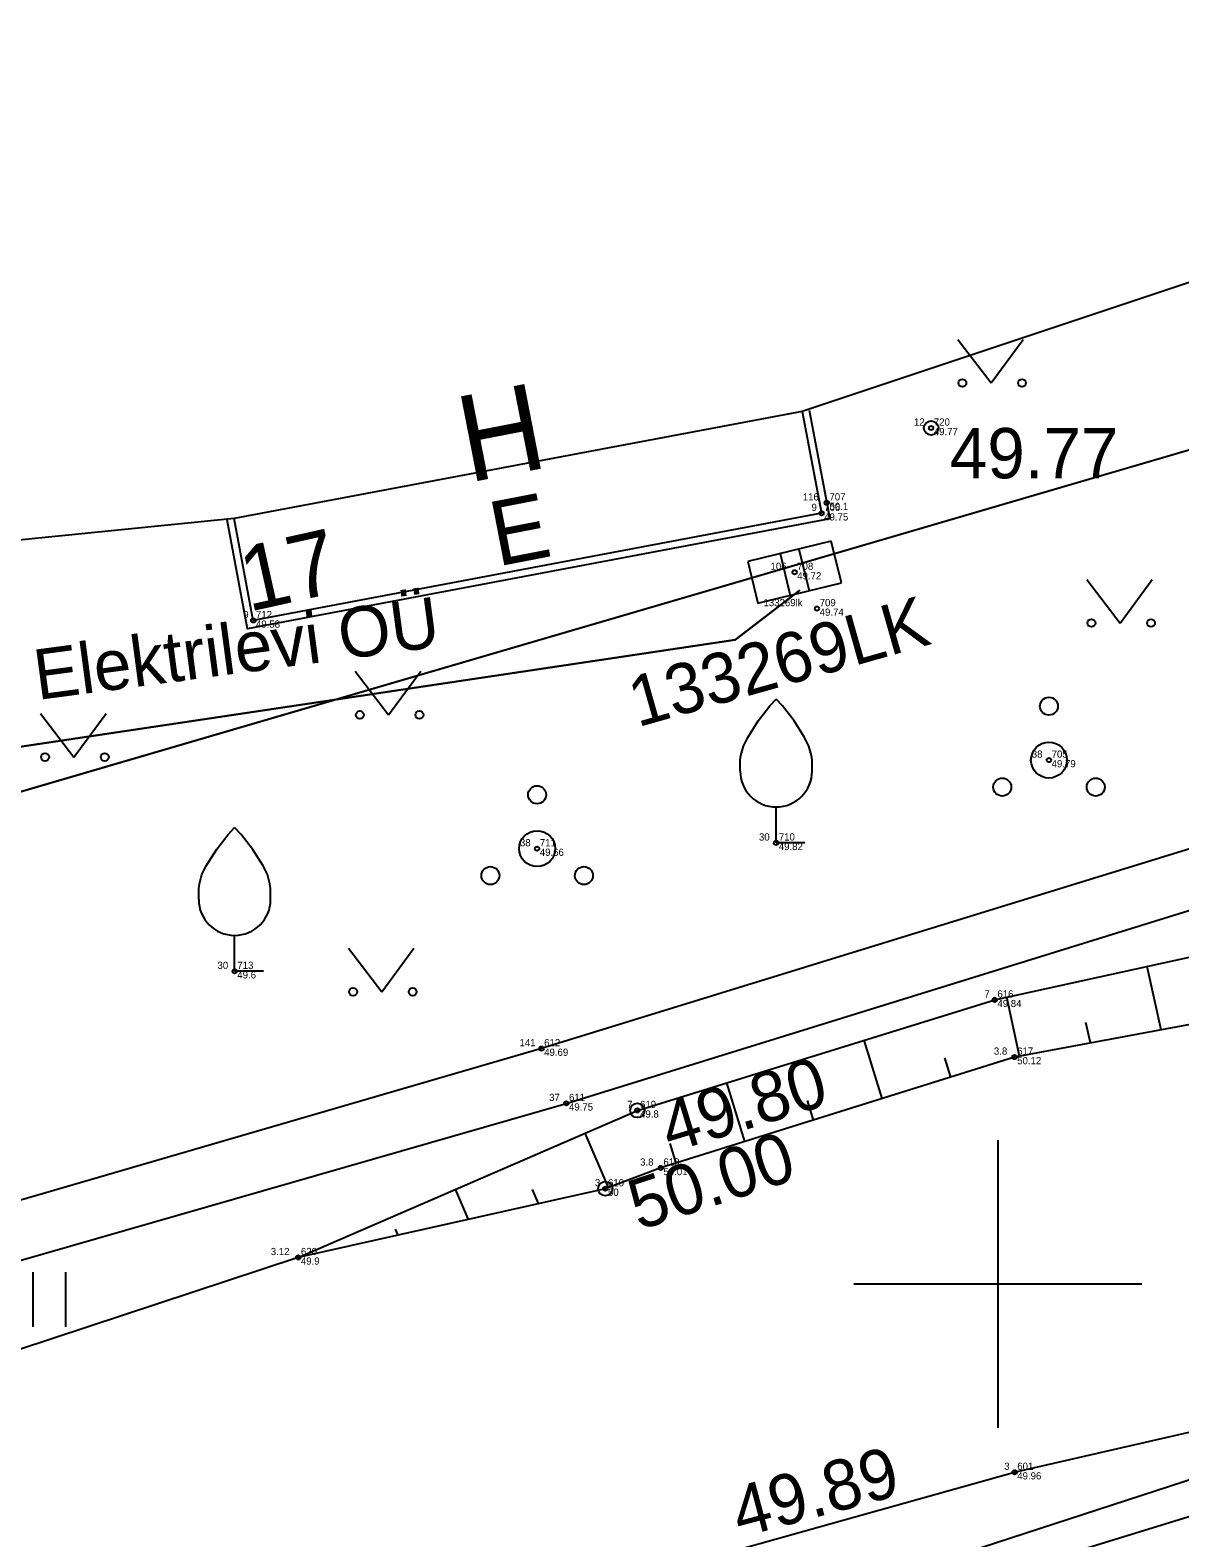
# Model space of a CAD drawing. Extents: x 543497 to 552146, y 6567125 to 6579845.
# Drawn here: x 546036.55 to 546052.53, y 6577696.47 to 6577717.44 of the extents above; entities that cross this region are included whole.
import ezdxf

# ---------------------------------------------------------------- set-up
doc = ezdxf.new("R2010")
doc.units = 0
for name, color, linetype in [('xref_Kangru tee 1_geodeesia$0$AED', 7, 'Continuous'), ('xref_Kangru tee 1_geodeesia$0$ELRAJATISMP', 7, 'Continuous'), ('xref_Kangru tee 1_geodeesia$0$HALJASTUS', 7, 'Continuous'), ('xref_Kangru tee 1_geodeesia$0$HOONE', 7, 'Continuous'), ('xref_Kangru tee 1_geodeesia$0$HOONEDET', 7, 'Continuous'), ('xref_Kangru tee 1_geodeesia$0$korgus-EH2000', 7, 'Continuous'), ('xref_Kangru tee 1_geodeesia$0$mootkood', 7, 'Continuous'), ('xref_Kangru tee 1_geodeesia$0$MOOTKORG-eh2000', 7, 'Continuous'), ('xref_Kangru tee 1_geodeesia$0$mootmpunkt', 7, 'Continuous'), ('xref_Kangru tee 1_geodeesia$0$MOOTNR', 7, 'Continuous'), ('xref_Kangru tee 1_geodeesia$0$MOOTPIIR', 7, 'Continuous'), ('xref_Kangru tee 1_geodeesia$0$MPKAABEL', 7, 'Continuous'), ('xref_Kangru tee 1_geodeesia$0$PIIR', 7, 'Continuous'), ('xref_Kangru tee 1_geodeesia$0$PUU', 7, 'Continuous'), ('xref_Kangru tee 1_geodeesia$0$RELJEEF', 7, 'Continuous'), ('xref_Kangru tee 1_geodeesia$0$SITRASS', 7, 'Continuous'), ('xref_Kangru tee 1_geodeesia$0$TEE', 7, 'Continuous'), ('xref_Kangru tee 1_geodeesia$0$vork', 7, 'Continuous')]:
    doc.layers.add(name, color=color, linetype=linetype)

# ---------------------------------------------------------------- blocks, each defined once
blk = doc.blocks.new('xref_Kangru tee 1_geodeesia$0$PQQSAS')
for centre, radius in [((0, 1.5), 0.25), ((0, 0), 0.5), ((-1.3, -0.75), 0.25), ((1.3, -0.75), 0.25)]:
    blk.add_circle(centre, radius)
blk = doc.blocks.new('xref_Kangru tee 1_geodeesia$0$VILJA1')
for p, q in [((0, 0), (0, 1)), ((0.8, 0), (0, 0))]:
    blk.add_line(p, q)
for points in [[(-1, 2), (-1, 2.3), (-0.98, 2.43), (-0.91, 2.69), (-0.79, 2.93), (-0.5, 3.4), (-0.18, 3.81), (0, 4)], [(1, 2), (1, 2.3), (0.98, 2.43), (0.91, 2.69), (0.79, 2.93), (0.5, 3.4), (0.18, 3.81), (0, 4)]]:
    blk.add_lwpolyline(points)
blk.add_arc((0, 2), 1, 180, 0)
blk = doc.blocks.new('xref_Kangru tee 1_geodeesia$0$hein')
for p, q in [((-0.455, 0.761), (-0.455, -0.761)), ((0.455, 0.761), (0.455, -0.761))]:
    blk.add_line(p, q)
blk = doc.blocks.new('xref_Kangru tee 1_geodeesia$0$MURU')
for p, q in [((-0.927, 1.213), (0, 0)), ((0, 0), (0.891, 1.213))]:
    blk.add_line(p, q)
for centre in [(-0.802, 0), (0.856, 0)]:
    blk.add_circle(centre, 0.11)
blk = doc.blocks.new('xref_Kangru tee 1_geodeesia$0$ELKAPP')
for p, q in [((1.195, 0.597), (-1.195, 0.597)), ((-1.195, 0.597), (-1.195, -0.597)), ((-0.271, 0.597), (-0.271, -0.597)), ((0.271, 0.597), (0.271, -0.597)), ((1.195, -0.597), (1.195, 0.597)), ((-1.195, -0.597), (1.195, -0.597))]:
    blk.add_line(p, q)
blk = doc.blocks.new('xref_Kangru tee 1_geodeesia$0$VKORIS')
for p, q in [((0, 4), (0, -4)), ((-4, 0), (4, 0))]:
    blk.add_line(p, q)

msp = doc.modelspace()

# ---------------------------------------------------------------- linework, layer by layer
at = {"layer": 'xref_Kangru tee 1_geodeesia$0$AED'}
msp.add_lwpolyline([(546059.838, 6577715.079), (546060.599, 6577708.494), (546043.656, 6577703.273), (546024.552, 6577697.712), (546024.121, 6577700.643), (546019.535, 6577705.044)], dxfattribs=at)
at = {"layer": 'xref_Kangru tee 1_geodeesia$0$HALJASTUS'}
msp.add_lwpolyline([(546028.276, 6577697.987), (546044.001, 6577702.512), (546059.639, 6577707.358), (546060.383, 6577708.688), (546059.561, 6577713.105)], dxfattribs=at)
at = {"layer": 'xref_Kangru tee 1_geodeesia$0$HOONE'}
msp.add_lwpolyline([(546047.281, 6577712.138), (546047.549, 6577710.72), (546039.649, 6577709.229), (546039.381, 6577710.647)], dxfattribs=at)
at = {"layer": 'xref_Kangru tee 1_geodeesia$0$HOONEDET'}
msp.add_lwpolyline([(546047.378, 6577712.157), (546047.664, 6577710.641), (546039.57, 6577709.114), (546039.284, 6577710.629)], dxfattribs=at)
at = {"layer": 'xref_Kangru tee 1_geodeesia$0$korgus-EH2000'}
for centre in [(546049.073, 6577711.907), (546044.989, 6577702.414), (546044.543, 6577701.325)]:
    msp.add_circle(centre, 0.1, dxfattribs=at)
at = {"layer": 'xref_Kangru tee 1_geodeesia$0$mootmpunkt'}
for centre in [(546049.073, 6577711.907), (546047.622, 6577710.866), (546047.549, 6577710.72), (546047.174, 6577709.901), (546047.486, 6577709.395), (546039.649, 6577709.229), (546050.711, 6577707.287), (546046.918, 6577706.135), (546043.595, 6577706.055), (546039.39, 6577704.349), (546049.957, 6577703.951), (546043.656, 6577703.273), (546050.232, 6577703.156), (546044.001, 6577702.512), (546044.989, 6577702.414), (546045.314, 6577701.613), (546044.543, 6577701.325), (546040.274, 6577700.368), (546050.233, 6577697.38)]:
    msp.add_circle(centre, 0.03, dxfattribs=at)
at = {"layer": 'xref_Kangru tee 1_geodeesia$0$MOOTPIIR'}
msp.add_lwpolyline([(546091.362, 6577730.835), (546076.174, 6577727.357), (546069.665, 6577722.185), (546069.859, 6577718.295), (546059.732, 6577716.292), (546047.281, 6577712.138), (546039.381, 6577710.647), (546032.006, 6577709.907), (546022.782, 6577705.611), (546019.535, 6577705.044), (546019.82, 6577703.764), (546018.234, 6577702.863), (546014.32, 6577701.586), (545991.87, 6577693.345), (545969.52, 6577687.243)], dxfattribs=at)
at = {"layer": 'xref_Kangru tee 1_geodeesia$0$MPKAABEL'}
for points in [[(546047.243, 6577709.648), (546047.243, 6577709.648), (546047.243, 6577709.648), (546047.243, 6577709.648), (546047.243, 6577709.648), (546046.35, 6577708.96), (546028.9, 6577706.35), (546020.34, 6577704.86), (546016.42, 6577703.78), (546014.701, 6577704.002)], [(546014.701, 6577704.002), (546016.42, 6577703.78), (546020.34, 6577704.86), (546028.9, 6577706.35), (546028.9, 6577706.35), (546046.35, 6577708.96), (546047.243, 6577709.648), (546047.243, 6577709.648), (546047.243, 6577709.648), (546047.243, 6577709.648)]]:
    msp.add_lwpolyline(points, dxfattribs=at)
at = {"layer": 'xref_Kangru tee 1_geodeesia$0$PIIR'}
for points in [[(545983.53, 6577775.51), (546081.11, 6577806.12), (546096.86, 6577764.18), (546079.41, 6577756.98), (546054.12, 6577754.83), (546055.48, 6577740.79), (546080.65, 6577742.83), (546099.69, 6577747.34), (546110.26, 6577728.46), (545969.55, 6577687.28), (545983.53, 6577775.51)], [(545526.72, 6577483.94), (545567.61, 6577503.92), (545600.27, 6577519.26), (545639.76, 6577537.43), (545673.8, 6577552.72), (545712.72, 6577569.73), (545743.83, 6577582.87), (545764.02, 6577591.24), (545805.47, 6577607.21), (545907.89, 6577644.25), (545925.88, 6577650.4), (545918.84, 6577672.45), (545921.7, 6577673.29), (545969.55, 6577687.28), (546110.26, 6577728.46), (546113.86, 6577718.6), (546117.94, 6577707.48), (546328.8, 6577761.79)]]:
    msp.add_lwpolyline(points, dxfattribs=at)
at = {"layer": 'xref_Kangru tee 1_geodeesia$0$PUU'}
msp.add_lwpolyline([(546117.866, 6577717.426), (546113.699, 6577716.286), (546090.767, 6577709.285), (546067.25, 6577701.449), (546060.951, 6577699.314), (546047.057, 6577695.034), (546019.897, 6577686.031), (545997.772, 6577678.867)], dxfattribs=at)
at = {"layer": 'xref_Kangru tee 1_geodeesia$0$RELJEEF'}
for p, q in [((546052.269, 6577703.535), (546052.076, 6577704.416)), ((546050.303, 6577703.169), (546050.123, 6577703.987)), ((546051.286, 6577703.352), (546051.224, 6577703.635)), ((546048.392, 6577702.579), (546048.142, 6577703.389)), ((546049.347, 6577702.878), (546049.263, 6577703.147)), ((546046.484, 6577701.98), (546046.231, 6577702.798)), ((546047.438, 6577702.279), (546047.354, 6577702.551)), ((546044.589, 6577701.342), (546044.261, 6577702.098)), ((546045.53, 6577701.681), (546045.445, 6577701.955)), ((546042.64, 6577700.898), (546042.458, 6577701.316)), ((546043.615, 6577701.117), (546043.53, 6577701.314)), ((546041.664, 6577700.68), (546041.628, 6577700.761))]:
    msp.add_line(p, q, dxfattribs=at)
msp.add_lwpolyline([(546040.274, 6577700.368), (546044.989, 6577702.414), (546049.957, 6577703.951), (546056.042, 6577705.287), (546059.025, 6577705.273)], dxfattribs=at)
at = {"layer": 'xref_Kangru tee 1_geodeesia$0$SITRASS'}
msp.add_lwpolyline([(545908.485, 6577643.705), (545911.194, 6577646.612), (545925.706, 6577656.002), (545927.481, 6577656.734), (545938.042, 6577659.913), (545948.418, 6577663.054), (545958.853, 6577666.457), (545971.932, 6577670.246), (545983.129, 6577674.156), (545994.132, 6577677.914), (546005.032, 6577681.831), (546015.499, 6577685.452), (546025.557, 6577688.556), (546030.559, 6577690.213), (546046.952, 6577695.414), (546066.518, 6577701.793), (546078.972, 6577705.852), (546100.203, 6577712.621), (546110.553, 6577715.537), (546117.41, 6577717.31), (546125.411, 6577719.428), (546136.464, 6577722.314), (546141.561, 6577723.784)], dxfattribs=at)
at = {"layer": 'xref_Kangru tee 1_geodeesia$0$TEE'}
for points in [[(545971.433, 6577672.366), (545997.276, 6577680.49), (546019.075, 6577687.637), (546046.227, 6577696.261), (546050.233, 6577697.38), (546060.833, 6577699.813), (546062.092, 6577700.466), (546063.421, 6577702.15), (546066.8, 6577702.917), (546090.631, 6577711.146), (546112.837, 6577718.304), (546121.35, 6577721.07), (546120.4, 6577725.737), (546111.41, 6577723.208), (546088.914, 6577715.843), (546065.816, 6577706.486), (546065.244, 6577706.703), (546065.037, 6577707.357), (546065.171, 6577709.425), (546065.38, 6577710.653), (546064.96, 6577714.947), (546067.921, 6577716.792), (546070.994, 6577716.678), (546072.733, 6577718.476)], [(546059.977, 6577715.174), (546061.866, 6577715.362), (546062.121, 6577710.624), (546061.045, 6577709.272), (546060.882, 6577708.001), (546060.893, 6577706.804), (546060.369, 6577705.849), (546059.158, 6577705.188), (546056.387, 6577704.301), (546050.232, 6577703.156), (546045.314, 6577701.613), (546044.543, 6577701.325), (546040.274, 6577700.368), (546017.855, 6577692.963), (545995.651, 6577685.598), (545969.99, 6577676.752), (545949.859, 6577670.253), (545932.117, 6577664.712), (545929.387, 6577664.046), (545924.424, 6577663.904), (545920.826, 6577664.534), (545918.964, 6577665.384), (545916.564, 6577667.08), (545914.824, 6577669.08)]]:
    msp.add_lwpolyline(points, dxfattribs=at)

# ---------------------------------------------------------------- block references
at = {"layer": 'xref_Kangru tee 1_geodeesia$0$ELRAJATISMP', "xscale": 0.5, "yscale": 0.5, "rotation": 13.580242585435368}
msp.add_blockref('xref_Kangru tee 1_geodeesia$0$ELKAPP', (546047.174, 6577709.901), dxfattribs=at)
at = {"layer": 'xref_Kangru tee 1_geodeesia$0$HALJASTUS', "xscale": 0.5, "yscale": 0.5}
for name, p in [('xref_Kangru tee 1_geodeesia$0$MURU', (546049.908, 6577712.533)), ('xref_Kangru tee 1_geodeesia$0$MURU', (546051.702, 6577709.194)), ('xref_Kangru tee 1_geodeesia$0$MURU', (546041.531, 6577707.916)), ('xref_Kangru tee 1_geodeesia$0$MURU', (546037.156, 6577707.329)), ('xref_Kangru tee 1_geodeesia$0$MURU', (546041.437, 6577704.063)), ('xref_Kangru tee 1_geodeesia$0$hein', (546036.812, 6577699.785))]:
    msp.add_blockref(name, p, dxfattribs=at)
at = {"layer": 'xref_Kangru tee 1_geodeesia$0$PUU', "xscale": 0.5, "yscale": 0.5}
for name, p in [('xref_Kangru tee 1_geodeesia$0$VILJA1', (546046.918, 6577706.135)), ('xref_Kangru tee 1_geodeesia$0$PQQSAS', (546050.711, 6577707.287)), ('xref_Kangru tee 1_geodeesia$0$PQQSAS', (546043.595, 6577706.055)), ('xref_Kangru tee 1_geodeesia$0$VILJA1', (546039.39, 6577704.349))]:
    msp.add_blockref(name, p, dxfattribs=at)
at = {"layer": 'xref_Kangru tee 1_geodeesia$0$vork', "xscale": 0.5, "yscale": 0.5}
msp.add_blockref('xref_Kangru tee 1_geodeesia$0$VKORIS', (546050, 6577700), dxfattribs=at)

# ---------------------------------------------------------------- texts
at = {"layer": 'xref_Kangru tee 1_geodeesia$0$ELRAJATISMP'}
msp.add_text('133269LK', height=0.7, rotation=15.8431, dxfattribs=at).set_placement((546044.991, 6577707.741))
at = {"layer": 'xref_Kangru tee 1_geodeesia$0$HOONE'}
for s, height, rotation, p in [('H', 1.2, 11.0067, (546042.637, 6577711.144)), ('E', 0.9, 10.9613, (546043.042, 6577709.978)), ('17', 0.9, 12.6035, (546039.583, 6577709.347))]:
    msp.add_text(s, height=height, rotation=rotation, dxfattribs=at).set_placement(p)
at = {"layer": 'xref_Kangru tee 1_geodeesia$0$korgus-EH2000'}
msp.add_text(' 49.77 ', height=0.7, dxfattribs=at).set_placement((546049.073, 6577711.207))
for s, rotation, p in [(' 49.80 ', 17.0395, (546045.194, 6577701.745)), (' 50.00 ', 18.1268, (546044.761, 6577700.66)), (' 49.89 ', 14.9536, (546046.163, 6577696.402))]:
    msp.add_text(s, height=0.7, rotation=rotation, dxfattribs=at).set_placement(p)
at = {"layer": 'xref_Kangru tee 1_geodeesia$0$mootkood'}
for s, p in [(' 12', (546048.797, 6577711.94)), (' 116', (546047.251, 6577710.899)), (' 9', (546047.373, 6577710.753)), (' 106', (546046.803, 6577709.934)), (' 133269lk', (546046.705, 6577709.428)), (' 9', (546039.473, 6577709.262)), (' 38', (546050.435, 6577707.32)), (' 38', (546043.319, 6577706.088)), (' 30', (546046.642, 6577706.168)), (' 30', (546039.114, 6577704.382)), (' 7', (546049.776, 6577703.984)), (' 141', (546043.313, 6577703.306)), (' 3.8', (546049.908, 6577703.189)), (' 37', (546043.725, 6577702.545)), (' 7', (546044.808, 6577702.447)), (' 3.8', (546044.99, 6577701.646)), (' 3', (546044.362, 6577701.358)), (' 3.12', (546039.855, 6577700.401)), (' 3', (546050.052, 6577697.413))]:
    msp.add_text(s, height=0.1, dxfattribs=at).set_placement(p)
at = {"layer": 'xref_Kangru tee 1_geodeesia$0$MOOTKORG-eh2000'}
for s, p in [(' 49.77', (546049.073, 6577711.807)), (' 50.1', (546047.622, 6577710.766)), (' 49.75', (546047.549, 6577710.62)), (' 49.72', (546047.174, 6577709.801)), (' 49.74', (546047.486, 6577709.295)), (' 49.58', (546039.649, 6577709.129)), (' 49.79', (546050.711, 6577707.187)), (' 49.66', (546043.595, 6577705.955)), (' 49.82', (546046.918, 6577706.035)), (' 49.6', (546039.39, 6577704.249)), (' 49.84', (546049.957, 6577703.851)), (' 49.69', (546043.656, 6577703.173)), (' 50.12', (546050.232, 6577703.056)), (' 49.75', (546044.001, 6577702.412)), (' 49.8', (546044.989, 6577702.314)), (' 50.01', (546045.314, 6577701.513)), (' 50', (546044.543, 6577701.225)), (' 49.9', (546040.274, 6577700.268)), (' 49.96', (546050.233, 6577697.28))]:
    msp.add_text(s, height=0.1, dxfattribs=at).set_placement(p)
at = {"layer": 'xref_Kangru tee 1_geodeesia$0$MOOTNR'}
for s, p in [(' 720', (546049.073, 6577711.94)), (' 707', (546047.622, 6577710.899)), (' 706', (546047.549, 6577710.753)), (' 708', (546047.174, 6577709.934)), (' 709', (546047.486, 6577709.428)), (' 712', (546039.649, 6577709.262)), (' 705', (546050.711, 6577707.32)), (' 711', (546043.595, 6577706.088)), (' 710', (546046.918, 6577706.168)), (' 713', (546039.39, 6577704.382)), (' 616', (546049.957, 6577703.984)), (' 612', (546043.656, 6577703.306)), (' 617', (546050.232, 6577703.189)), (' 611', (546044.001, 6577702.545)), (' 619', (546044.989, 6577702.447)), (' 618', (546045.314, 6577701.646)), (' 610', (546044.543, 6577701.358)), (' 620', (546040.274, 6577700.401)), (' 601', (546050.233, 6577697.413))]:
    msp.add_text(s, height=0.1, dxfattribs=at).set_placement(p)
at = {"layer": 'xref_Kangru tee 1_geodeesia$0$MPKAABEL'}
msp.add_text('Elektrilevi OÜ', height=0.7, rotation=7.5795, dxfattribs=at).set_placement((546036.649, 6577708.122))

doc.saveas('drawing.dxf')
